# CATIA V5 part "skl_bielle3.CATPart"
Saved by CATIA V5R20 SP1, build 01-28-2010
Part number: skl_bielle3
Publications: "Droite.1", "Droite.2", "Droite.3", "Plan xy"
Bounding box of the stored display mesh (mm): x 638.046 to 668.11, y 509.145 to 1028.275, z -100 to 0
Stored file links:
  C:\Users\Manon\Desktop\IAO\SKL_rlanglais\skl_bielle3.CATPart
  C:\Users\Manon\Desktop\IAO\SKL_rlanglais\SKL_rlanglais.CATProduct
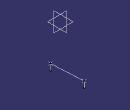
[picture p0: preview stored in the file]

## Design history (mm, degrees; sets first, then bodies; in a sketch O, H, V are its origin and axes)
Set1
  Point1 "D": linked copy from another document
  Point2 "C": linked copy from another document
Set2
  Line1: type PtPt, FirstPoint Point1, SecondPoint Point2
  Point3 "D": linked copy from another document
  Line2: type Normal, RefPoint Point2, RefSkin xy-plane, Start 0, End 100
  Line3: type Normal, RefPoint Point1, RefSkin xy-plane, Start 0, End 100
Body1 (main body)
